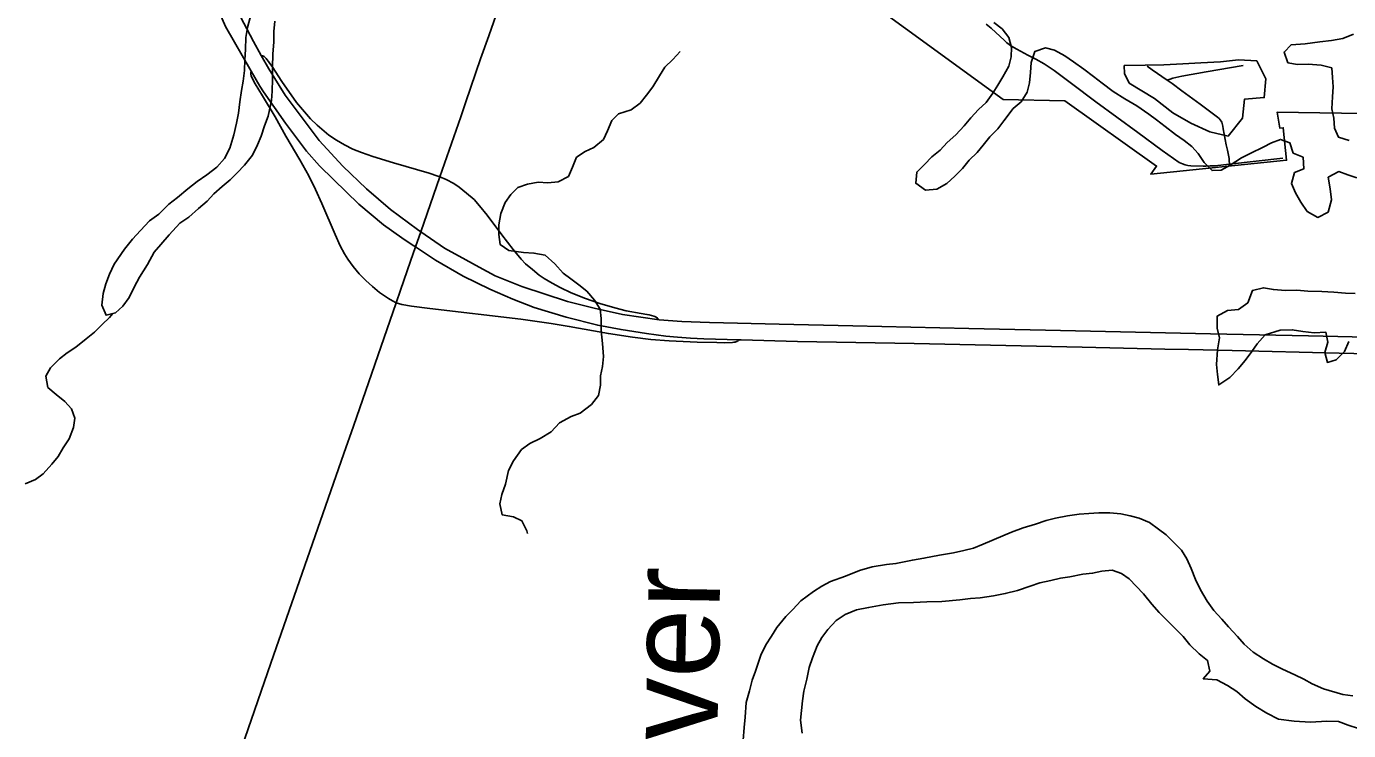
# Model space of a CAD drawing. Extents: x 0 to 34, y 0 to 22.
# Drawn here: x 2.7 to 4.044, y 17.296 to 18.011 of the extents above; entities that cross this region are included whole.
import ezdxf

# ---------------------------------------------------------------- set-up
doc = ezdxf.new("R2010")
doc.units = 0
for name, color, linetype in [('GM_X_City_Street', 7, 'Continuous'), ('GM_X_Corporation', 7, 'Continuous'), ('GM_X_Interchange_Ramps', 7, 'Continuous'), ('GM_X_Major_River', 7, 'Continuous'), ('GM_X_Minor_River', 7, 'Continuous'), ('GM_X_Minor_River_Text', 7, 'Continuous'), ('GM_X_State_Route', 7, 'Continuous')]:
    doc.layers.add(name, color=color, linetype=linetype)

msp = doc.modelspace()

# ---------------------------------------------------------------- linework, layer by layer
at = {"layer": 'GM_X_City_Street'}
for points in [[(3.6757, 18.0132), (3.6806, 18.0093), (3.6942, 17.9965), (3.6965, 17.9944), (3.7015, 17.9909), (3.7068, 17.9877), (3.7178, 17.9819), (3.7262, 17.9777), (3.7344, 17.9731), (3.7448, 17.9662), (3.7624, 17.9531), (3.7872, 17.9343), (3.8299, 17.9033), (3.8545, 17.8849), (3.8719, 17.8727), (3.875, 17.8712), (3.8778, 17.8704), (3.8807, 17.8697), (3.8837, 17.8693), (3.8961, 17.8688), (3.899, 17.8688), (3.9032, 17.8692), (3.9083, 17.8694), (3.917, 17.8703), (3.9228, 17.871), (3.9771, 17.8771)], [(3.9228, 17.871), (3.9226, 17.8746), (3.9225, 17.8767), (3.922, 17.88), (3.921, 17.8851), (3.9197, 17.8907), (3.9166, 17.9069), (3.9161, 17.9095), (3.9155, 17.9123), (3.915, 17.9138), (3.9146, 17.9147), (3.9136, 17.916), (3.9124, 17.9173), (3.9107, 17.9187), (3.893, 17.9318), (3.8744, 17.9455), (3.8645, 17.9528), (3.8597, 17.9562), (3.8443, 17.9669), (3.8393, 17.9706)], [(3.8597, 17.9562), (3.8625, 17.9572), (3.8655, 17.9583), (3.8746, 17.9604), (3.8993, 17.9647), (3.9368, 17.9711)]]:
    msp.add_lwpolyline(points, dxfattribs=at)
at = {"layer": 'GM_X_Corporation'}
msp.add_lwpolyline([(2.1, 20.7089), (2.1, 19.0206), (2.3914, 19.0139), (3.2392, 18.3106), (3.2398, 18.2919), (3.237, 18.2477), (3.2287, 18.2095), (3.2216, 18.1771), (3.2145, 18.1554), (3.2499, 18.1545), (3.2739, 18.153), (3.3988, 18.1506), (3.6928, 17.9367), (3.7557, 17.9354), (3.8488, 17.8691), (3.8429, 17.8609), (3.981, 17.875), (3.9776, 17.908), (3.974, 17.9077), (3.9713, 17.9238), (4.7767, 17.9112)], dxfattribs=at)
at = {"layer": 'GM_X_Interchange_Ramps'}
for points in [[(3.1203, 17.8582), (3.1183, 17.8589), (3.1095, 17.8617), (3.0733, 17.8725), (3.0523, 17.8787), (3.0405, 17.8828), (3.0318, 17.8864), (3.0234, 17.8906), (3.0153, 17.8953), (3.0076, 17.9006), (3.0026, 17.9044), (2.9955, 17.9105), (2.9889, 17.9171), (2.9826, 17.9241), (2.9747, 17.9338), (2.9595, 17.9549), (2.9499, 17.9701), (2.9476, 17.9733), (2.946, 17.9754), (2.9445, 17.9773), (2.9438, 17.9783), (2.9431, 17.979), (2.9425, 17.9797), (2.9417, 17.9803), (2.941, 17.9806), (2.9399, 17.9811), (2.9386, 17.9813)], [(2.9284, 17.9654), (2.9281, 17.9638), (2.9281, 17.9624), (2.9284, 17.9608), (2.929, 17.9592), (2.9326, 17.9527), (2.9401, 17.9405), (2.953, 17.9192), (2.9638, 17.8996), (2.9781, 17.8755), (2.9871, 17.8591), (2.994, 17.8452), (3.0004, 17.831), (3.0138, 17.7994), (3.019, 17.7881), (3.0235, 17.7799), (3.0267, 17.7746), (3.0321, 17.7669), (3.0382, 17.7597), (3.0449, 17.7528), (3.0518, 17.7466), (3.0591, 17.7407), (3.0682, 17.7346), (3.0723, 17.7321), (3.0759, 17.73)], [(3.3433, 17.713), (3.3416, 17.7144), (3.3401, 17.7156), (3.3387, 17.7163), (3.3377, 17.7167), (3.3353, 17.7174), (3.3331, 17.7178), (3.3307, 17.7183), (3.3248, 17.7193), (3.3095, 17.7219), (3.298, 17.7251), (3.283, 17.7294), (3.2683, 17.7345), (3.2539, 17.7404), (3.2426, 17.7457), (3.2343, 17.75), (3.2262, 17.7548), (3.2211, 17.7583), (3.2144, 17.7639), (3.2074, 17.7699), (3.203, 17.7745), (3.1947, 17.7843), (3.1833, 17.7993), (3.1685, 17.8192), (3.1606, 17.8288), (3.155, 17.835), (3.1475, 17.8417), (3.1398, 17.8477), (3.1344, 17.8512), (3.1266, 17.8554), (3.1203, 17.8582)], [(3.0759, 17.73), (3.0816, 17.7285), (3.0915, 17.7268), (3.11, 17.7244), (3.2026, 17.7135), (3.2334, 17.7092), (3.2518, 17.7062), (3.2916, 17.6989), (3.3162, 17.6952), (3.3347, 17.693), (3.3533, 17.6914), (3.3819, 17.6901), (3.4017, 17.6898), (3.4099, 17.6895), (3.4178, 17.6899), (3.4191, 17.69), (3.4206, 17.6903), (3.4219, 17.6907), (3.4226, 17.691), (3.4232, 17.6914), (3.4238, 17.6919), (3.4242, 17.6926)]]:
    msp.add_lwpolyline(points, dxfattribs=at)
at = {"layer": 'GM_X_Major_River'}
for points in [[(2.9286, 18.0238), (2.9249, 18.0097), (2.923, 17.9998), (2.9227, 17.9876), (2.922, 17.977), (2.9217, 17.9663), (2.9203, 17.9553), (2.9188, 17.9458), (2.917, 17.9344), (2.9156, 17.9229), (2.9137, 17.9127), (2.9108, 17.9009), (2.9067, 17.8871), (2.9015, 17.8768), (2.8935, 17.8681), (2.8833, 17.86), (2.8735, 17.8535), (2.8641, 17.8458), (2.8535, 17.837), (2.8448, 17.8305), (2.8346, 17.8202), (2.8252, 17.8133), (2.8161, 17.8037), (2.8078, 17.7949), (2.7999, 17.7846), (2.7894, 17.7693), (2.7845, 17.7594), (2.7808, 17.7495), (2.7782, 17.7396), (2.7767, 17.7278), (2.781, 17.7175), (2.7905, 17.7199), (2.798, 17.7268), (2.8044, 17.7356), (2.8097, 17.7459), (2.8149, 17.7562), (2.8232, 17.7691), (2.8299, 17.7817), (2.8367, 17.7894), (2.845, 17.7993), (2.8559, 17.8112), (2.865, 17.8173), (2.8748, 17.8261), (2.8839, 17.8334), (2.8907, 17.8407), (2.899, 17.8483), (2.9073, 17.8552), (2.9141, 17.8621), (2.9216, 17.8701), (2.9299, 17.8801), (2.9348, 17.8907), (2.9385, 17.8995), (2.9419, 17.9098), (2.9456, 17.9197), (2.9493, 17.9357), (2.95, 17.9452), (2.9503, 17.9574), (2.9502, 17.9692), (2.9505, 17.9832), (2.9515, 17.995), (2.9515, 18.0057), (2.9525, 18.0163)], [(3.6834, 18.0148), (3.6918, 18.0084), (3.6987, 17.9997), (3.7014, 17.9895), (3.7011, 17.98), (3.6985, 17.9705), (3.6925, 17.9598), (3.6876, 17.9514), (3.6824, 17.943), (3.6756, 17.9338), (3.6677, 17.9265), (3.6601, 17.9181), (3.6534, 17.9101), (3.6447, 17.9009), (3.636, 17.8929), (3.6288, 17.8852), (3.6202, 17.8783), (3.613, 17.8707), (3.6051, 17.863), (3.604, 17.8516), (3.6139, 17.8445), (3.6253, 17.8457), (3.6355, 17.8514), (3.6438, 17.8587), (3.6514, 17.8667), (3.6582, 17.8751), (3.6665, 17.8828), (3.6725, 17.8904), (3.6793, 17.8989), (3.6876, 17.9069), (3.6936, 17.9149), (3.703, 17.9275), (3.7113, 17.9344), (3.7173, 17.944), (3.7195, 17.9535), (3.7206, 17.9641), (3.7213, 17.9744), (3.725, 17.9854), (3.736, 17.9893), (3.7451, 17.9867), (3.7554, 17.9811), (3.7642, 17.975), (3.7749, 17.9675), (3.7848, 17.96), (3.7936, 17.9532), (3.8047, 17.9449), (3.8165, 17.9374), (3.8287, 17.9302), (3.8409, 17.9219), (3.8486, 17.9159), (3.8574, 17.9091), (3.868, 17.9012), (3.8768, 17.8952), (3.8845, 17.8891), (3.891, 17.8819), (3.8971, 17.8728), (3.9052, 17.8645), (3.9146, 17.865), (3.9237, 17.87), (3.9351, 17.8773), (3.9445, 17.8823), (3.957, 17.8884), (3.9657, 17.8927), (3.9748, 17.8961), (3.9844, 17.8928), (3.9878, 17.8822), (3.9977, 17.878), (3.9986, 17.8663), (3.9891, 17.8624), (3.9858, 17.8514), (3.99, 17.8419), (3.9954, 17.8324), (4.0019, 17.8229), (4.0126, 17.8169), (4.0232, 17.8223), (4.0265, 17.8349), (4.0253, 17.8459), (4.0233, 17.8577), (4.0339, 17.8634), (4.0431, 17.8601), (4.0522, 17.8571)], [(4.027, 17.9273), (4.0277, 17.9394), (4.0284, 17.9497), (4.0276, 17.9592), (4.0268, 17.9687), (4.0161, 17.9717), (4.0028, 17.9727), (3.9922, 17.9723), (3.9823, 17.9741), (3.9784, 17.9848), (3.9856, 17.9924), (4, 17.9933), (4.0148, 17.9953), (4.0266, 17.9968), (4.0383, 17.9988), (4.0489, 18.0031)], [(3.8208, 17.9533), (3.8466, 17.9377), (3.8652, 17.9233), (3.8835, 17.9127), (3.9028, 17.904), (3.9215, 17.8995), (3.9363, 17.9178), (3.9382, 17.9372), (3.9583, 17.9387), (3.9598, 17.9577), (3.9507, 17.9759), (3.9321, 17.977), (3.9139, 17.9751), (3.8937, 17.9739), (3.8755, 17.9731), (3.8561, 17.9719), (3.8371, 17.9715), (3.8157, 17.9714)], [(3.8157, 17.9714), (3.8161, 17.9631), (3.8208, 17.9533)], [(4.0447, 17.8951), (4.0337, 17.8984), (4.0295, 17.9075), (4.029, 17.9178), (4.027, 17.9273)], [(4.0508, 17.7396), (4.0409, 17.7399), (4.0291, 17.741), (4.0169, 17.7417), (4.0025, 17.742), (3.9915, 17.743), (3.9797, 17.7426), (3.9675, 17.7436), (3.9576, 17.7455), (3.9463, 17.7427), (3.9414, 17.7302), (3.932, 17.7233), (3.9209, 17.7224), (3.9104, 17.7167), (3.9104, 17.7045), (3.9128, 17.6946), (3.9106, 17.6824), (3.9096, 17.6676)], [(3.9096, 17.6676), (3.9108, 17.6574), (3.912, 17.6467), (3.9233, 17.6544), (3.9316, 17.6632), (3.9388, 17.6716), (3.9456, 17.6808), (3.9512, 17.6884), (3.9591, 17.6976), (3.9743, 17.7022), (3.9868, 17.7027), (3.9975, 17.7009), (4.0089, 17.6998), (4.021, 17.7003), (4.023, 17.69), (4.02, 17.6797), (4.0224, 17.6695), (4.0315, 17.6722), (4.0398, 17.6806), (4.0443, 17.6909)], [(3.8883, 17.4489), (3.884, 17.4602), (3.8794, 17.4701), (3.874, 17.4788), (3.8587, 17.4943), (3.8507, 17.5003), (3.8415, 17.5071), (3.8312, 17.5112), (3.8221, 17.5138), (3.8126, 17.5157), (3.8012, 17.5168), (3.7902, 17.5167), (3.7799, 17.5162), (3.7701, 17.5154), (3.7583, 17.5138), (3.7462, 17.5115), (3.7367, 17.5091), (3.7257, 17.5053), (3.7132, 17.5014), (3.7014, 17.4971), (3.6927, 17.4933), (3.6726, 17.4848), (3.6628, 17.4809), (3.6529, 17.4786), (3.6423, 17.4762), (3.6283, 17.4738), (3.6123, 17.4707), (3.6006, 17.4687), (3.5839, 17.4652), (3.5744, 17.4644), (3.5596, 17.462), (3.5467, 17.4581), (3.5327, 17.4523), (3.5175, 17.4469), (3.5085, 17.4423), (3.5001, 17.4369), (3.4873, 17.4273), (3.479, 17.4185), (3.4718, 17.4116), (3.4628, 17.4002), (3.4575, 17.3914), (3.4515, 17.3826), (3.4466, 17.372), (3.4411, 17.3559), (3.4377, 17.3468), (3.4351, 17.3358), (3.4318, 17.324), (3.4307, 17.3091), (3.4297, 17.2988), (3.4286, 17.2859)], [(3.4886, 17.2928), (3.487, 17.306), (3.4888, 17.3258), (3.4902, 17.3357), (3.4932, 17.3479), (3.4957, 17.3597), (3.4991, 17.3696), (3.5039, 17.3818), (3.5084, 17.3902), (3.5145, 17.3982), (3.5231, 17.4074), (3.5322, 17.4135), (3.5439, 17.4182), (3.5561, 17.4205), (3.5709, 17.4233), (3.5864, 17.4253), (3.6016, 17.4258), (3.6153, 17.4262), (3.6305, 17.4267), (3.6487, 17.4283), (3.6597, 17.4296), (3.6696, 17.4304), (3.6829, 17.4324), (3.695, 17.4347), (3.7075, 17.4378), (3.7204, 17.4421), (3.7303, 17.4456), (3.7413, 17.4479), (3.7511, 17.4503), (3.7606, 17.4519), (3.7739, 17.4546), (3.7838, 17.4554), (3.7933, 17.4574), (3.8035, 17.4586), (3.813, 17.4552), (3.821, 17.4496), (3.8356, 17.4345), (3.844, 17.4239), (3.8513, 17.4156), (3.8605, 17.4065), (3.8685, 17.3986), (3.8758, 17.391), (3.8827, 17.3827), (3.8922, 17.3736), (3.9006, 17.3668), (3.903, 17.3558), (3.8962, 17.3482), (3.9099, 17.3471), (3.9209, 17.3415), (3.9305, 17.3354), (3.9389, 17.3279), (3.9496, 17.32), (3.961, 17.3132), (3.9728, 17.3072), (3.9888, 17.305), (4.0051, 17.304), (4.0219, 17.3052), (4.0336, 17.3049), (4.0435, 17.3012), (4.0542, 17.2978)], [(4.0483, 17.3309), (4.038, 17.3323), (4.0186, 17.3379), (4.0068, 17.3432), (3.9984, 17.3477), (3.9892, 17.3522), (3.9767, 17.3578), (3.9667, 17.3631), (3.9576, 17.3683), (3.9469, 17.3751), (3.9377, 17.3834), (3.9312, 17.391), (3.922, 17.4008), (3.9151, 17.4087), (3.9071, 17.4174), (3.9002, 17.4269), (3.8933, 17.4386), (3.8883, 17.4489)]]:
    msp.add_lwpolyline(points, dxfattribs=at)
at = {"layer": 'GM_X_Minor_River'}
for points in [[(3.3645, 17.9855), (3.357, 17.9774), (3.3491, 17.9694), (3.3434, 17.9606), (3.3367, 17.9495), (3.3303, 17.9411), (3.3239, 17.9331), (3.3148, 17.9262), (3.3019, 17.9223), (3.2951, 17.9154), (3.2906, 17.9048), (3.2865, 17.896), (3.2767, 17.888), (3.268, 17.8837), (3.2593, 17.878), (3.2552, 17.8681), (3.2511, 17.8585), (3.2405, 17.8531), (3.2302, 17.8519), (3.2203, 17.8526), (3.2093, 17.8507), (3.1995, 17.8472), (3.1923, 17.8403), (3.1867, 17.8319), (3.1822, 17.8208), (3.1804, 17.8094), (3.1801, 17.7995), (3.1817, 17.7893), (3.1904, 17.7832), (3.2053, 17.7814), (3.2159, 17.7807), (3.2273, 17.7785), (3.2372, 17.7698), (3.2457, 17.7604), (3.2533, 17.7544), (3.2617, 17.7483), (3.2697, 17.7419), (3.2774, 17.7328), (3.2831, 17.7238), (3.2844, 17.7143), (3.2844, 17.7017), (3.2857, 17.6888), (3.2865, 17.6755), (3.2855, 17.6656), (3.2836, 17.6561), (3.2837, 17.6466), (3.2815, 17.6359), (3.2743, 17.6267), (3.263, 17.6179), (3.2539, 17.6148), (3.2418, 17.6083), (3.2335, 17.5991), (3.2221, 17.5922), (3.2119, 17.5872), (3.2032, 17.5811), (3.1953, 17.5696), (3.1901, 17.5597), (3.1871, 17.546), (3.1834, 17.5353), (3.1812, 17.5258), (3.1836, 17.5148), (3.195, 17.5126), (3.2037, 17.5088), (3.2087, 17.4986), (3.2095, 17.4959)], [(2.7769, 17.708), (2.7844, 17.7153), (2.7878, 17.7192)], [(2.6986, 17.5463), (2.7092, 17.5506), (2.7172, 17.5563), (2.7258, 17.5662), (2.7322, 17.5739), (2.7375, 17.5827), (2.7435, 17.5918), (2.748, 17.6033), (2.7494, 17.6128), (2.7459, 17.6223), (2.7391, 17.6298), (2.7303, 17.637), (2.7219, 17.6442), (2.7199, 17.6556), (2.7244, 17.664), (2.7338, 17.6731), (2.7414, 17.6793), (2.7501, 17.685), (2.7607, 17.6935), (2.7693, 17.7004), (2.7769, 17.708)]]:
    msp.add_lwpolyline(points, dxfattribs=at)
at = {"layer": 'GM_X_State_Route'}
for points in [[(2.8487, 18.9689), (2.8515, 18.8476), (2.8536, 18.7761), (2.8569, 18.6331), (2.8571, 18.6236), (2.8592, 18.546), (2.8606, 18.4838), (2.8613, 18.4278), (2.8622, 18.3469), (2.8632, 18.3067), (2.864, 18.2664), (2.8663, 18.2297), (2.8675, 18.2156), (2.8692, 18.1958), (2.8716, 18.1741), (2.8749, 18.1525), (2.8785, 18.1342), (2.8827, 18.116), (2.8875, 18.0979), (2.8938, 18.077), (2.9007, 18.0586), (2.9144, 18.0271), (2.9309, 17.9955), (2.9386, 17.9813)], [(2.8406, 18.6373), (2.8439, 18.5065), (2.8504, 18.2422), (2.8517, 18.2143), (2.8526, 18.2015), (2.8531, 18.1957), (2.8553, 18.1767), (2.8614, 18.1397), (2.8669, 18.1137), (2.8771, 18.0767), (2.8908, 18.0373), (2.9023, 18.0109), (2.9284, 17.9654), (2.9374, 17.9503), (2.941, 17.9446), (2.9635, 17.9125), (2.9847, 17.8843), (2.9979, 17.8694), (3.0121, 17.8554), (3.0378, 17.8303), (3.0629, 17.8093), (3.0816, 17.7961), (3.0923, 17.789)], [(3.1467, 17.9344), (3.1616, 17.9781), (3.1701, 18.0014), (3.1752, 18.0161), (3.1906, 18.0602), (3.2072, 18.1071), (3.2252, 18.1581)], [(2.9386, 17.9813), (2.9463, 17.9679), (2.9632, 17.9412), (2.9976, 17.8949), (3.0218, 17.8691), (3.0456, 17.8458), (3.0701, 17.825), (3.0977, 17.8046), (3.101, 17.8024), (3.1251, 17.7855), (3.1467, 17.7738), (3.1601, 17.7663), (3.1766, 17.7575), (3.2036, 17.7468), (3.2501, 17.7314), (3.277, 17.7248), (3.306, 17.7182), (3.3433, 17.713), (3.3662, 17.7113), (3.3943, 17.7101), (3.4653, 17.7085), (3.5399, 17.7066), (3.6581, 17.7042), (3.7358, 17.7023), (3.9037, 17.6986), (4.0032, 17.6965), (4.1368, 17.6935)], [(3.0906, 17.7725), (3.0956, 17.7869), (3.101, 17.8024), (3.1203, 17.8582), (3.1415, 17.9192), (3.1467, 17.9344)], [(3.0923, 17.789), (3.0956, 17.7869), (3.1159, 17.7735), (3.1439, 17.7571), (3.1711, 17.744), (3.1944, 17.7338), (3.2162, 17.7254), (3.2486, 17.7154), (3.2807, 17.7073), (3.3045, 17.7029), (3.3302, 17.6988), (3.3501, 17.6962), (3.3617, 17.6953), (3.3752, 17.6941), (3.3886, 17.6937), (3.4242, 17.6926), (3.4265, 17.6924), (3.4839, 17.6909), (3.6024, 17.6889), (3.7733, 17.6851), (3.8572, 17.6831), (3.8813, 17.6826)], [(3.0759, 17.73), (3.0804, 17.7429), (3.0906, 17.7725)], [(3.0228, 17.5772), (3.0325, 17.6048), (3.0759, 17.73)], [(3.8813, 17.6826), (3.9256, 17.6818), (4.0343, 17.6791), (4.1399, 17.6767), (4.2393, 17.6743), (4.3546, 17.6719), (4.3697, 17.6716)], [(2.7821, 16.8763), (2.7839, 16.8847), (2.787, 16.8967), (2.7906, 16.9086), (2.8286, 17.0205), (2.8625, 17.1173), (2.8902, 17.1966), (2.9087, 17.2494), (2.9486, 17.364), (3.0068, 17.5314), (3.0228, 17.5772)]]:
    msp.add_lwpolyline(points, dxfattribs=at)

# ---------------------------------------------------------------- texts
at = {"layer": 'GM_X_Minor_River_Text'}
msp.add_text('River', height=0.09475, rotation=89.0015, dxfattribs=at).set_placement((3.4002, 17.1653))

doc.saveas('drawing.dxf')
